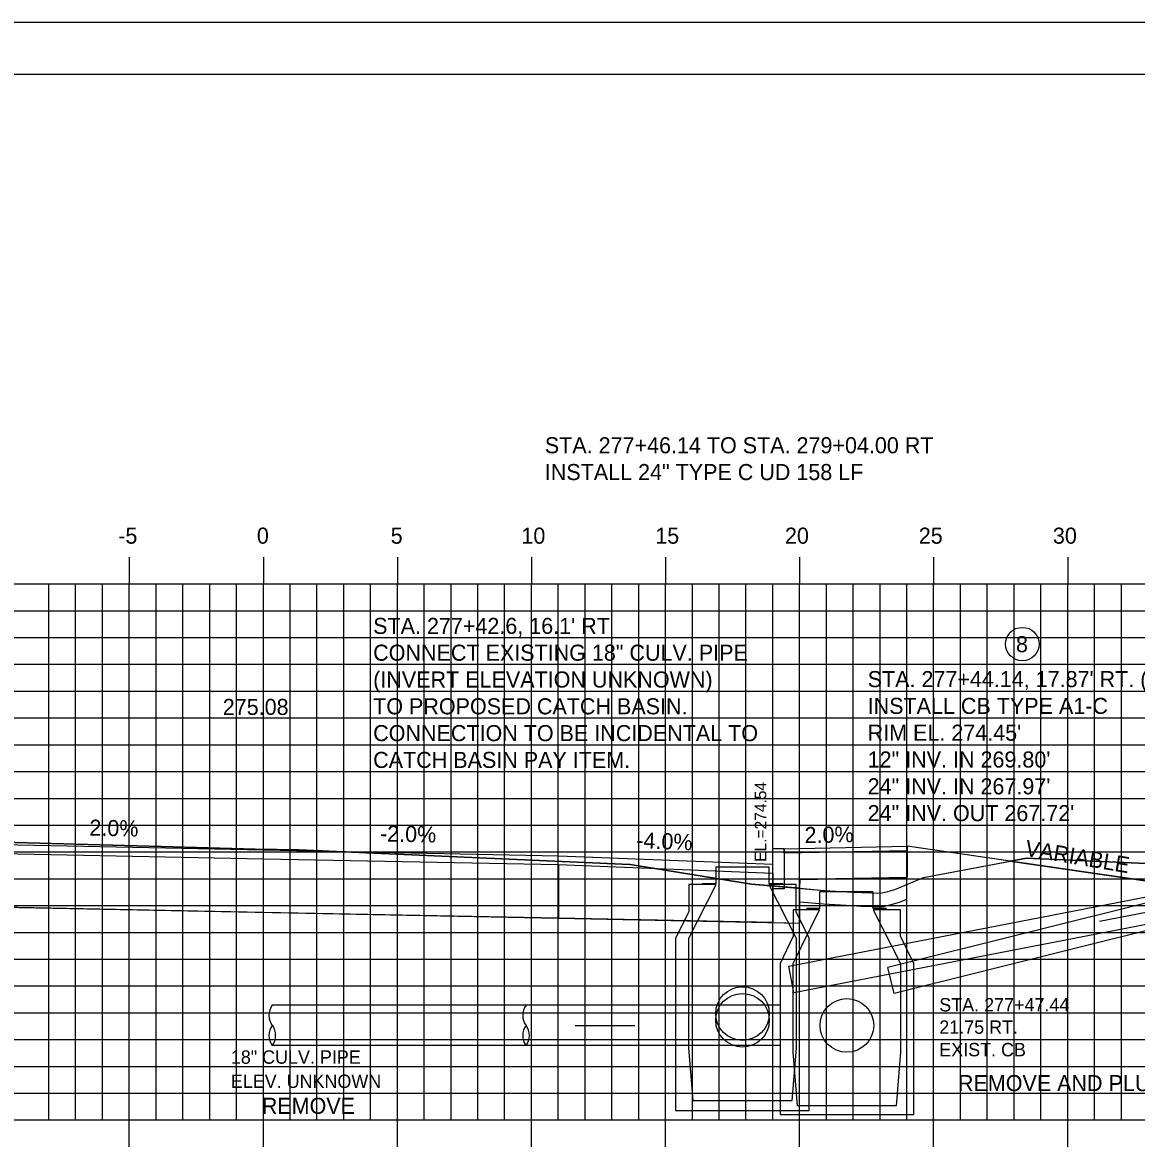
# Model space of a CAD drawing. Extents: x 854231 to 854401, y 366268 to 366378.
# Drawn here: x 854304.79 to 854346.33, y 366335.99 to 366378.18 of the extents above; entities that cross this region are included whole.
import ezdxf

# ---------------------------------------------------------------- set-up
doc = ezdxf.new("R2010")
doc.units = 0
for name, color, linetype in [('ANNOTATION', 7, 'Continuous'), ('BORDER', 7, 'Continuous'), ('D_Curb_Type_1_Rt', 7, 'Continuous'), ('D_Drainage_CB_TypeA1-B1', 7, 'Continuous'), ('D_Drainage_Culvert', 7, 'Continuous'), ('D_Drainage_Text', 7, 'Continuous'), ('D_Roadway_Centerline_Text', 7, 'Continuous'), ('D_Roadway_Edge_TW', 7, 'Continuous'), ('D_Roadway_FinishedGrade', 7, 'Continuous'), ('D_Roadway_Sidewalks_Paved', 7, 'Continuous'), ('D_Roadway_SubGrade', 7, 'Continuous'), ('D_Text_Monospaced', 7, 'Continuous'), ('D_Text_Standard', 7, 'Continuous'), ('H_V ANNOTATION', 7, 'Continuous'), ('JUNK COM EXC', 7, 'Continuous'), ('JUNK FILL', 7, 'Continuous'), ('MAJOR', 7, 'Continuous'), ('MINOR', 7, 'Continuous'), ('PDRAIN', 7, 'Continuous'), ('PLOT BOUNDARY', 7, 'Continuous'), ('S_Drainage_CB', 7, 'Continuous'), ('S_Drainage_Culvert_Top', 7, 'Continuous'), ('S_Roadway_Centerline', 7, 'Continuous')]:
    doc.layers.add(name, color=color, linetype=linetype)

msp = doc.modelspace()

# ---------------------------------------------------------------- linework, layer by layer
at = {"layer": 'ANNOTATION'}
for p, q in [((854347.15, 366345.064), (854344.962, 366344.64)), ((854325.402, 366340.766), (854327.631, 366340.766))]:
    msp.add_line(p, q, dxfattribs=at)
at = {"layer": 'BORDER'}
msp.add_line((854398.771, 366376.236), (854238.771, 366376.236), dxfattribs=at)
at = {"layer": 'D_Curb_Type_1_Rt'}
msp.add_lwpolyline([(854333.191, 366347.359), (854333.191, 366345.859), (854332.775, 366345.859), (854332.775, 366347.359)], close=True, dxfattribs=at)
at = {"layer": 'D_Drainage_CB_TypeA1-B1'}
for p, q in [((854329.64, 366346.021), (854329.64, 366345.004)), ((854329.64, 366344.02), (854330.657, 366346.021)), ((854330.657, 366346.021), (854329.64, 366346.021)), ((854333.642, 366346.021), (854332.625, 366346.021)), ((854332.625, 366346.021), (854333.642, 366344.02)), ((854333.642, 366345.004), (854333.642, 366346.021)), ((854329.64, 366345.004), (854329.147, 366344.02)), ((854334.134, 366344.02), (854333.642, 366345.004)), ((854329.147, 366344.02), (854329.147, 366337.596)), ((854329.64, 366339.925), (854329.64, 366344.02)), ((854333.642, 366344.02), (854333.642, 366339.925)), ((854334.134, 366337.596), (854334.134, 366344.02)), ((854329.804, 366337.956), (854329.64, 366339.925)), ((854333.642, 366339.925), (854333.478, 366337.956)), ((854329.147, 366337.596), (854334.134, 366337.596)), ((854333.478, 366337.956), (854329.804, 366337.956))]:
    msp.add_line(p, q, dxfattribs=at)
msp.add_lwpolyline([(854330.132, 366346.063), (854330.657, 366346.063), (854330.657, 366346.686), (854332.625, 366346.686), (854332.625, 366346.063), (854333.15, 366346.063)], dxfattribs=at)
at = {"layer": 'D_Drainage_Culvert'}
for p, q in [((854333.367, 366342.974), (854351.039, 366346.398)), ((854333.559, 366341.992), (854351.23, 366345.416)), ((854333.559, 366341.992), (854333.367, 366342.974)), ((854329.64, 366341.514), (854323.572, 366341.514)), ((854329.64, 366340.014), (854323.572, 366340.014))]:
    msp.add_line(p, q, dxfattribs=at)
for centre, start, end in [((854324.072, 366341.139), 143.1301, 216.8699), ((854324.072, 366340.389), 143.1301, 216.8699), ((854323.072, 366340.389), 323.1301, 36.8699)]:
    msp.add_arc(centre, 0.625, start, end, dxfattribs=at)
at = {"layer": 'D_Drainage_Text'}
msp.add_circle((854342.078, 366354.991), 0.625, dxfattribs=at)
at = {"layer": 'D_Roadway_Edge_TW'}
msp.add_lwpolyline([(854294.775, 366347.215), (854302.775, 366347.535), (854324.775, 366347.095), (854332.771, 366346.775)], dxfattribs=at)
at = {"layer": 'D_Roadway_FinishedGrade'}
msp.add_line((854351.455, 366345.46), (854337.78, 366347.45), dxfattribs=at)
at = {"layer": 'D_Roadway_Sidewalks_Paved'}
msp.add_lwpolyline([(854333.192, 366347.358), (854337.78, 366347.45), (854337.78, 366347.283), (854333.192, 366347.191)], close=True, dxfattribs=at)
at = {"layer": 'D_Roadway_SubGrade'}
msp.add_line((854337.771, 366345.479), (854337.771, 366346.021), dxfattribs=at)
for points in [[(854332.779, 366344.602), (854333.779, 366344.582), (854333.779, 366346.204), (854337.781, 366346.283), (854337.781, 366347.283)], [(854333.779, 366345.379), (854334.667, 366345.301), (854335.723, 366345.241), (854336.081, 366345.218), (854336.834, 366345.191), (854337.185, 366345.276), (854337.492, 366345.362), (854337.771, 366345.479)]]:
    msp.add_lwpolyline(points, dxfattribs=at)
for points in [[(854302.775, 366345.202), (854302.775, 366347.202), (854313.775, 366346.982), (854324.775, 366346.762), (854324.775, 366344.762), (854313.775, 366344.982)], [(854324.775, 366346.762), (854332.775, 366346.442), (854332.775, 366344.602), (854324.775, 366344.762)]]:
    msp.add_lwpolyline(points, close=True, dxfattribs=at)
at = {"layer": 'JUNK COM EXC'}
for points in [[(854302.775, 366345.202), (854324.775, 366344.762), (854333.779, 366344.582), (854333.779, 366345.881), (854331.98, 366346.04), (854327.524, 366346.755), (854327.464, 366346.764), (854327.445, 366346.765), (854315.1, 366347.314), (854313.464, 366347.342), (854309.962, 366347.434), (854302.686, 366347.633)], [(854352.085, 366345.555), (854352.421, 366345.589), (854352.825, 366345.615), (854352.081, 366345.582), (854349.832, 366346.714), (854346.696, 366346.81), (854342.237, 366347.004), (854341.629, 366346.89), (854351.455, 366345.459)]]:
    msp.add_lwpolyline(points, dxfattribs=at)
at = {"layer": 'JUNK FILL'}
msp.add_lwpolyline([(854333.779, 366345.881), (854334.703, 366345.799), (854335.753, 366345.74), (854336.106, 366345.717), (854336.783, 366345.694), (854337.059, 366345.76), (854337.328, 366345.835), (854338.396, 366346.282), (854341.629, 366346.89), (854337.78, 366347.45), (854337.78, 366347.283), (854337.781, 366346.283), (854333.779, 366346.204), (854333.771, 366345.882)], close=True, dxfattribs=at)
at = {"layer": 'MAJOR'}
for p, q in [((854308.771, 366358.238), (854308.771, 366357.236)), ((854313.771, 366358.238), (854313.771, 366357.236)), ((854318.771, 366358.238), (854318.771, 366357.236)), ((854323.771, 366358.238), (854323.771, 366357.236)), ((854328.771, 366358.238), (854328.771, 366357.236)), ((854333.771, 366358.238), (854333.771, 366357.236)), ((854338.771, 366358.238), (854338.771, 366357.236)), ((854343.771, 366358.238), (854343.771, 366357.236)), ((854243.771, 366357.236), (854383.771, 366357.236)), ((854243.771, 366357.236), (854383.771, 366357.236)), ((854308.771, 366337.236), (854308.771, 366357.236)), ((854313.771, 366337.236), (854313.771, 366357.236)), ((854318.771, 366337.236), (854318.771, 366357.236)), ((854323.771, 366337.236), (854323.771, 366357.236)), ((854328.771, 366337.236), (854328.771, 366357.236)), ((854333.771, 366337.236), (854333.771, 366357.236)), ((854338.771, 366337.236), (854338.771, 366357.236)), ((854343.771, 366337.236), (854343.771, 366357.236)), ((854243.771, 366352.236), (854383.771, 366352.236)), ((854243.771, 366347.236), (854383.771, 366347.236)), ((854243.771, 366342.236), (854383.771, 366342.236)), ((854243.771, 366337.236), (854383.771, 366337.236)), ((854243.771, 366337.236), (854383.771, 366337.236)), ((854308.771, 366336.234), (854308.771, 366337.236)), ((854313.771, 366336.234), (854313.771, 366337.236)), ((854318.771, 366336.234), (854318.771, 366337.236)), ((854323.771, 366336.234), (854323.771, 366337.236)), ((854328.771, 366336.234), (854328.771, 366337.236)), ((854333.771, 366336.234), (854333.771, 366337.236)), ((854338.771, 366336.234), (854338.771, 366337.236)), ((854343.771, 366336.234), (854343.771, 366337.236))]:
    msp.add_line(p, q, dxfattribs=at)
at = {"layer": 'MINOR'}
for p, q in [((854305.771, 366337.236), (854305.771, 366357.236)), ((854306.771, 366337.236), (854306.771, 366357.236)), ((854307.771, 366337.236), (854307.771, 366357.236)), ((854309.771, 366337.236), (854309.771, 366357.236)), ((854310.771, 366337.236), (854310.771, 366357.236)), ((854311.771, 366337.236), (854311.771, 366357.236)), ((854312.771, 366337.236), (854312.771, 366357.236)), ((854314.771, 366337.236), (854314.771, 366357.236)), ((854315.771, 366337.236), (854315.771, 366357.236)), ((854316.771, 366337.236), (854316.771, 366357.236)), ((854317.771, 366337.236), (854317.771, 366357.236)), ((854319.771, 366337.236), (854319.771, 366357.236)), ((854320.771, 366337.236), (854320.771, 366357.236)), ((854321.771, 366337.236), (854321.771, 366357.236)), ((854322.771, 366337.236), (854322.771, 366357.236)), ((854324.771, 366337.236), (854324.771, 366357.236)), ((854325.771, 366337.236), (854325.771, 366357.236)), ((854326.771, 366337.236), (854326.771, 366357.236)), ((854327.771, 366337.236), (854327.771, 366357.236)), ((854329.771, 366337.236), (854329.771, 366357.236)), ((854330.771, 366337.236), (854330.771, 366357.236)), ((854331.771, 366337.236), (854331.771, 366357.236)), ((854332.771, 366337.236), (854332.771, 366357.236)), ((854334.771, 366337.236), (854334.771, 366357.236)), ((854335.771, 366337.236), (854335.771, 366357.236)), ((854336.771, 366337.236), (854336.771, 366357.236)), ((854337.771, 366337.236), (854337.771, 366357.236)), ((854339.771, 366337.236), (854339.771, 366357.236)), ((854340.771, 366337.236), (854340.771, 366357.236)), ((854341.771, 366337.236), (854341.771, 366357.236)), ((854342.771, 366337.236), (854342.771, 366357.236)), ((854344.771, 366337.236), (854344.771, 366357.236)), ((854345.771, 366337.236), (854345.771, 366357.236)), ((854243.771, 366356.236), (854383.771, 366356.236)), ((854243.771, 366355.236), (854383.771, 366355.236)), ((854243.771, 366354.236), (854383.771, 366354.236)), ((854243.771, 366353.236), (854383.771, 366353.236)), ((854243.771, 366351.236), (854383.771, 366351.236)), ((854243.771, 366350.236), (854383.771, 366350.236)), ((854243.771, 366349.236), (854383.771, 366349.236)), ((854243.771, 366348.236), (854383.771, 366348.236)), ((854243.771, 366346.236), (854383.771, 366346.236)), ((854243.771, 366345.236), (854383.771, 366345.236)), ((854243.771, 366344.236), (854383.771, 366344.236)), ((854243.771, 366343.236), (854383.771, 366343.236)), ((854243.771, 366341.236), (854383.771, 366341.236)), ((854243.771, 366340.236), (854383.771, 366340.236)), ((854243.771, 366339.236), (854383.771, 366339.236)), ((854243.771, 366338.236), (854383.771, 366338.236))]:
    msp.add_line(p, q, dxfattribs=at)
at = {"layer": 'PDRAIN'}
for centre in [(854331.641, 366341.206), (854331.641, 366340.956)]:
    msp.add_circle(centre, 1, dxfattribs=at)
at = {"layer": 'PLOT BOUNDARY'}
msp.add_lwpolyline([(854230.678, 366268.177), (854400.678, 366268.177), (854400.678, 366378.177), (854230.678, 366378.177)], close=True, dxfattribs=at)
at = {"layer": 'S_Drainage_CB'}
for p, q in [((854334.517, 366345.08), (854333.533, 366345.08)), ((854333.533, 366345.08), (854333.533, 366344.096)), ((854333.533, 366343.079), (854334.517, 366345.08)), ((854337.536, 366345.08), (854336.519, 366345.08)), ((854336.519, 366345.08), (854337.536, 366343.079)), ((854337.536, 366344.096), (854337.536, 366345.08)), ((854333.533, 366344.096), (854333.041, 366343.079)), ((854338.028, 366343.079), (854337.536, 366344.096)), ((854333.041, 366343.079), (854333.041, 366337.436)), ((854333.533, 366339.765), (854333.533, 366343.079)), ((854337.536, 366343.079), (854337.536, 366339.765)), ((854338.028, 366337.436), (854338.028, 366343.079)), ((854333.697, 366337.764), (854333.533, 366339.765)), ((854337.536, 366339.765), (854337.372, 366337.764)), ((854337.372, 366337.764), (854333.697, 366337.764)), ((854333.041, 366337.436), (854338.028, 366337.436))]:
    msp.add_line(p, q, dxfattribs=at)
msp.add_lwpolyline([(854337.011, 366345.122), (854336.519, 366345.122), (854336.519, 366345.745), (854334.517, 366345.745), (854334.517, 366345.122), (854334.025, 366345.122)], dxfattribs=at)
at = {"layer": 'S_Drainage_Culvert_Top'}
for p, q in [((854351.528, 366346.544), (854337.056, 366342.919)), ((854351.771, 366345.573), (854337.299, 366341.949)), ((854337.299, 366341.949), (854337.056, 366342.919)), ((854333.041, 366341.514), (854314.104, 366341.514)), ((854333.041, 366340.014), (854314.104, 366340.014))]:
    msp.add_line(p, q, dxfattribs=at)
msp.add_circle((854335.535, 366340.764), 1, dxfattribs=at)
for centre, radius, start, end in [((854314.604, 366341.139), 0.625, 143.1301, 216.8699), ((854314.604, 366340.389), 0.625, 143.1301, 216.8699), ((854313.558, 366340.404), 0.671, 324.4396, 33.373)]:
    msp.add_arc(centre, radius, start, end, dxfattribs=at)
at = {"layer": 'S_Roadway_Centerline'}
msp.add_lwpolyline([(854302.686, 366347.633), (854309.962, 366347.434), (854313.464, 366347.342), (854315.1, 366347.314), (854327.445, 366346.765), (854327.464, 366346.764), (854327.524, 366346.755), (854331.98, 366346.04), (854334.703, 366345.799), (854335.753, 366345.74), (854336.106, 366345.717), (854336.783, 366345.694), (854337.059, 366345.76), (854337.328, 366345.835), (854338.396, 366346.282), (854342.237, 366347.004), (854346.696, 366346.81), (854349.832, 366346.714), (854352.081, 366345.582), (854355.458, 366345.731), (854355.948, 366345.698), (854356.669, 366345.776), (854363.052, 366346.167), (854372.586, 366346.011)], dxfattribs=at)

# ---------------------------------------------------------------- texts
at = {"layer": 'ANNOTATION'}
for s, rotation, p in [('2.0%', 358.8542, (854307.279, 366347.845)), ('-2.0%', 358.8542, (854318.118, 366347.629)), ('2.0%', 1.1488, (854333.962, 366347.564)), ('-4.0%', 357.7094, (854327.672, 366347.38)), ('VARIABLE', 350.3758, (854342.149, 366347.096))]:
    msp.add_text(s, height=0.6, rotation=rotation, dxfattribs=at).set_placement(p)
for s, p in [('REMOVE AND PLUG', (854339.676, 366338.312)), ('REMOVE', (854313.713, 366337.465))]:
    msp.add_text(s, height=0.6, dxfattribs=at).set_placement(p)
at = {"layer": 'D_Drainage_Text'}
for s, p in [('STA. 277+46.14 TO STA. 279+04.00 RT', (854324.269, 366362.109)), ('INSTALL 24" TYPE C UD 158 LF', (854324.269, 366361.109)), ("STA. 277+42.6, 16.1' RT", (854317.867, 366355.37)), ('CONNECT EXISTING 18" CULV. PIPE', (854317.867, 366354.37)), ('(INVERT ELEVATION UNKNOWN)', (854317.867, 366353.37)), ("STA. 277+44.14, 17.87' RT. (1„)", (854336.309, 366353.385)), ('TO PROPOSED CATCH BASIN.', (854317.867, 366352.37)), ('INSTALL CB TYPE A1-C', (854336.309, 366352.385)), ('CONNECTION TO BE INCIDENTAL TO', (854317.867, 366351.37)), ("RIM EL. 274.45'", (854336.309, 366351.385)), ('CATCH BASIN PAY ITEM.', (854317.867, 366350.37)), ('12" INV. IN 269.80\'', (854336.309, 366350.385)), ('24" INV. IN 267.97\'', (854336.309, 366349.385)), ('24" INV. OUT 267.72\'', (854336.309, 366348.385))]:
    msp.add_text(s, height=0.6, dxfattribs=at).set_placement(p)
at = {"layer": 'D_Roadway_Centerline_Text'}
msp.add_text('275.08', height=0.6, dxfattribs=at).set_placement((854312.259, 366352.347))
at = {"layer": 'D_Text_Monospaced'}
for s, height, p in [('STA. 277+47.44', 0.49998, (854338.98, 366341.285)), ('21.75 RT.', 0.5, (854338.98, 366340.451)), ('EXIST. CB', 0.5, (854338.98, 366339.611)), ('18" CULV. PIPE', 0.49998, (854312.559, 366339.333)), ('ELEV. UNKNOWN', 0.49998, (854312.559, 366338.431))]:
    msp.add_text(s, height=height, dxfattribs=at).set_placement(p)
at = {"layer": 'D_Text_Standard'}
msp.add_text(' EL.=274.54', height=0.4335, rotation=90, dxfattribs=at).set_placement((854332.53, 366346.706))
at = {"layer": 'H_V ANNOTATION'}
for s, p in [('-5', (854308.361, 366358.736)), ('0', (854313.53, 366358.736)), ('5', (854318.522, 366358.736)), ('10', (854323.396, 366358.736)), ('15', (854328.388, 366358.736)), ('20', (854333.225, 366358.736)), ('25', (854338.217, 366358.736)), ('30', (854343.219, 366358.736)), ('8', (854341.84, 366354.687))]:
    msp.add_text(s, height=0.6, dxfattribs=at).set_placement(p)
at = {"layer": 'S_Roadway_Centerline'}
for s, p in [('C', (854315.094, 366347.314)), ('L', (854315.1, 366347.307))]:
    msp.add_text(s, height=0.0146, dxfattribs=at).set_placement(p)

doc.saveas('drawing.dxf')
